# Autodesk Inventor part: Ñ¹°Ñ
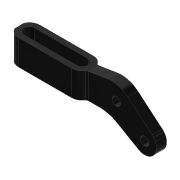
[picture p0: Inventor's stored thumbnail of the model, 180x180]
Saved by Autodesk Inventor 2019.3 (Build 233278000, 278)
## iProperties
Created: 2017-10
Part Number: Ñ¹°Ñ
Material: Ogólny
Document SubType Name: Modeling
Designer: CADENGINEERING4
Density: 1 g/cm^3
Appearance: Gładki — czarny
Author: CADENGINEERING4
Revision Number: ÈÎºÎ
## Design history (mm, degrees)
feature "ÇÐ³ý-À­Éì1"
node "Bryła1"
